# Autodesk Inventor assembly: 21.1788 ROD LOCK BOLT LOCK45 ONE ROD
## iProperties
Created: 2007-03
Part Number: 21.1788 ROD LOCK BOLT LOCK45 ONE ROD
Document SubType Name: Assembly
Designer: Andy Moles
Author: Andy Moles
